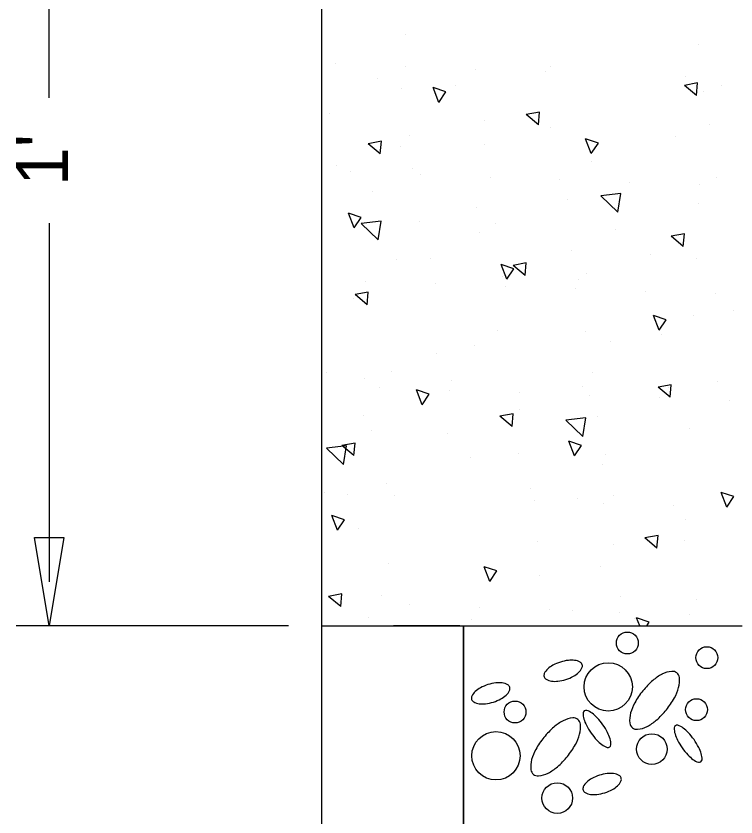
# Model space of a CAD drawing. Extents: x 0 to 8.5, y 0 to 11.
# Drawn here: x 4.506 to 5.34, y 7.415 to 8.342 of the extents above; entities that cross this region are included whole.
import ezdxf

# ---------------------------------------------------------------- set-up
doc = ezdxf.new("R2010")
doc.units = 0
for name, color, linetype in [('Default', 7, 'Continuous'), ('DTL-ASPHALT', 7, 'Continuous'), ('DTL-CONCRETE', 7, 'Continuous'), ('DTL-GRAVEL', 7, 'Continuous'), ('DTL-TEXT', 7, 'Continuous')]:
    doc.layers.add(name, color=color, linetype=linetype)

# ---------------------------------------------------------------- blocks, each defined once
blk = doc.blocks.new('POINT_DISPLAY')
at = {"layer": 'Default'}
blk.add_line((0, 0), (0, 0), dxfattribs=at)

msp = doc.modelspace()

# ---------------------------------------------------------------- linework, layer by layer
at = {"layer": 'DTL-ASPHALT'}
msp.add_lwpolyline([(5.02444, 7.05788), (4.86007, 7.05788), (4.86007, 7.63621), (5.02444, 7.63621)], close=True, dxfattribs=at)
at = {"layer": 'DTL-CONCRETE'}
for p, q in [((4.86007, 7.05788), (4.86007, 8.71374)), ((4.95736, 8.32082), (4.95736, 8.32082)), ((5.29682, 8.3088), (5.29682, 8.3088)), ((4.8758, 8.28674), (4.8758, 8.28674)), ((4.95686, 8.28378), (4.95686, 8.28378)), ((5.03792, 8.28082), (5.03792, 8.28082)), ((5.1249, 8.28374), (5.1249, 8.28374)), ((5.11899, 8.27786), (5.11899, 8.27786)), ((5.28111, 8.27193), (5.28111, 8.27193)), ((4.92465, 8.26947), (4.92465, 8.26947)), ((5.0154, 8.2623), (5.0154, 8.2623)), ((5.29557, 8.26477), (5.28031, 8.26196)), ((5.2943, 8.25022), (5.28031, 8.26196)), ((5.2943, 8.25022), (5.29557, 8.26477)), ((5.32376, 8.26158), (5.32376, 8.26158)), ((4.95307, 8.25807), (4.95307, 8.25807)), ((5.00401, 8.25435), (4.98929, 8.25929)), ((4.99584, 8.24223), (4.98929, 8.25928)), ((4.99584, 8.24223), (5.00401, 8.25435)), ((5.30213, 8.25515), (5.30213, 8.25515)), ((4.86916, 8.2299), (4.86916, 8.2299)), ((5.11241, 8.23099), (5.09714, 8.22817)), ((5.11113, 8.21643), (5.09714, 8.22817)), ((5.11113, 8.21643), (5.1124, 8.23099)), ((5.04843, 8.22103), (5.04843, 8.22103)), ((5.30896, 8.21658), (5.30896, 8.21658)), ((5.125, 8.21329), (5.125, 8.21329)), ((4.92924, 8.1972), (4.91398, 8.19438)), ((4.92796, 8.18264), (4.92924, 8.1972)), ((4.96193, 8.20395), (4.96193, 8.20395)), ((5.18059, 8.1951), (5.16587, 8.20004)), ((5.17242, 8.18298), (5.16587, 8.20003)), ((5.27029, 8.20324), (5.27029, 8.20324)), ((4.92796, 8.18264), (4.91397, 8.19438)), ((4.95187, 8.19083), (4.95187, 8.19083)), ((5.04911, 8.19401), (5.04911, 8.19401)), ((5.17242, 8.18298), (5.18059, 8.1951)), ((4.87719, 8.16894), (4.87719, 8.16894)), ((5.17286, 8.17361), (5.17286, 8.17361)), ((4.89294, 8.16171), (4.89294, 8.16171)), ((4.96521, 8.16584), (4.96521, 8.16584)), ((4.97401, 8.15875), (4.97401, 8.15875)), ((5.05507, 8.15579), (5.05507, 8.15579)), ((5.13613, 8.15283), (5.13613, 8.15283)), ((5.31699, 8.15562), (5.31699, 8.15562)), ((5.2172, 8.14987), (5.2172, 8.14987)), ((5.29826, 8.14691), (5.29826, 8.14691)), ((4.91916, 8.13948), (4.91916, 8.13948)), ((5.20646, 8.1369), (5.18333, 8.13421)), ((5.2031, 8.11524), (5.18333, 8.13421)), ((5.2031, 8.11524), (5.20646, 8.1369)), ((5.14515, 8.12995), (5.14515, 8.12995)), ((5.29664, 8.12516), (5.29664, 8.12516)), ((4.8978, 8.09688), (4.89125, 8.11393)), ((4.90597, 8.109), (4.89125, 8.11393)), ((5.03978, 8.12029), (5.03978, 8.12029)), ((4.8978, 8.09688), (4.90597, 8.10899)), ((4.92895, 8.10461), (4.90582, 8.10192)), ((4.92559, 8.08296), (4.92894, 8.10461)), ((4.97323, 8.10488), (4.97323, 8.10488)), ((4.92559, 8.08296), (4.90582, 8.10192)), ((5.06125, 8.10178), (5.06125, 8.10178)), ((5.20008, 8.09496), (5.20008, 8.09496)), ((5.04294, 8.09104), (5.04294, 8.09104)), ((5.28029, 8.09011), (5.26503, 8.0873)), ((5.27902, 8.07556), (5.26503, 8.0873)), ((5.27902, 8.07556), (5.28029, 8.09011)), ((5.14937, 8.07128), (5.14937, 8.07128)), ((4.94638, 8.06084), (4.94638, 8.06084)), ((4.98631, 8.06194), (4.98631, 8.06194)), ((5.24119, 8.06589), (5.24119, 8.06589)), ((5.29466, 8.06122), (5.29466, 8.06122)), ((5.07438, 8.03763), (5.06783, 8.05468)), ((5.08255, 8.04975), (5.06783, 8.05468)), ((5.07438, 8.03763), (5.08255, 8.04974)), ((5.09713, 8.05633), (5.08186, 8.05351)), ((5.09585, 8.04177), (5.08186, 8.05351)), ((5.09585, 8.04177), (5.09712, 8.05633)), ((5.06928, 8.04082), (5.06928, 8.04082)), ((5.16737, 8.04362), (5.16737, 8.04362)), ((4.9112, 8.03524), (4.9112, 8.03524)), ((4.99226, 8.03228), (4.99226, 8.03228)), ((5.15729, 8.03772), (5.15729, 8.03772)), ((4.91396, 8.02254), (4.8987, 8.01973)), ((4.91268, 8.00798), (4.91396, 8.02254)), ((5.07333, 8.02932), (5.07333, 8.02932)), ((5.15439, 8.02635), (5.15439, 8.02635)), ((5.23545, 8.02339), (5.23545, 8.02339)), ((5.31652, 8.02043), (5.31652, 8.02043)), ((4.89744, 8.01516), (4.89744, 8.01516)), ((4.91268, 8.00798), (4.89869, 8.01972)), ((4.91367, 8.00949), (4.91367, 8.00949)), ((5.33724, 8.00183), (5.33724, 8.00183)), ((5.25096, 7.97838), (5.24441, 7.99543)), ((5.25913, 7.9905), (5.24441, 7.99543)), ((5.29115, 7.99517), (5.29115, 7.99517)), ((5.25096, 7.97838), (5.25913, 7.99049)), ((5.06415, 7.97828), (5.06415, 7.97828)), ((5.16532, 7.97676), (5.16532, 7.97676)), ((5.19459, 7.96497), (5.19459, 7.96497)), ((5.25334, 7.97366), (5.25334, 7.97366)), ((5.03745, 7.96105), (5.03745, 7.96105)), ((4.99348, 7.9511), (4.99348, 7.9511)), ((4.86539, 7.92999), (4.86539, 7.92999)), ((4.94089, 7.93085), (4.94089, 7.93085)), ((5.17375, 7.92927), (5.17375, 7.92927)), ((4.90958, 7.92293), (4.90958, 7.92293)), ((5.01069, 7.91993), (5.01069, 7.91993)), ((5.31904, 7.91921), (5.31904, 7.91921)), ((4.92679, 7.91224), (4.92679, 7.91224)), ((4.97633, 7.89228), (4.96979, 7.90933)), ((4.98451, 7.90439), (4.96979, 7.90933)), ((5.00785, 7.90928), (5.00785, 7.90928)), ((5.16188, 7.91363), (5.16188, 7.91363)), ((5.26373, 7.9009), (5.24974, 7.91264)), ((5.26501, 7.91546), (5.24975, 7.91264)), ((5.26136, 7.9127), (5.26136, 7.9127)), ((5.26373, 7.9009), (5.26501, 7.91545)), ((4.97633, 7.89228), (4.9845, 7.90439)), ((5.08892, 7.90632), (5.08892, 7.90632)), ((5.16998, 7.90336), (5.16998, 7.90336)), ((5.25104, 7.9004), (5.25104, 7.9004)), ((5.33211, 7.89743), (5.33211, 7.89743)), ((5.08184, 7.88167), (5.06658, 7.87885)), ((5.08057, 7.86711), (5.08184, 7.88167)), ((5.08952, 7.88704), (5.08952, 7.88704)), ((4.90818, 7.8795), (4.90818, 7.8795)), ((5.08057, 7.86711), (5.06658, 7.87885)), ((5.16615, 7.87702), (5.14303, 7.87432)), ((5.16279, 7.85536), (5.14303, 7.87432)), ((5.16279, 7.85536), (5.16615, 7.87701)), ((5.28566, 7.86518), (5.28566, 7.86518)), ((4.9176, 7.86197), (4.9176, 7.86197)), ((5.00562, 7.85887), (5.00562, 7.85887)), ((4.88864, 7.84473), (4.86552, 7.84204)), ((4.89868, 7.84788), (4.88341, 7.84507)), ((4.8974, 7.83332), (4.88341, 7.84506)), ((4.88528, 7.82307), (4.88864, 7.84473)), ((4.8974, 7.83332), (4.89868, 7.84788)), ((5.15292, 7.83303), (5.14637, 7.85008)), ((5.16109, 7.84514), (5.14637, 7.85008)), ((5.15292, 7.83303), (5.16109, 7.84514)), ((4.88528, 7.82307), (4.86551, 7.84204)), ((5.08853, 7.83627), (5.08853, 7.83627)), ((5.1891, 7.83498), (5.1891, 7.83498)), ((5.03195, 7.83106), (5.03195, 7.83106)), ((5.18556, 7.82298), (5.18556, 7.82298)), ((4.93539, 7.80085), (4.93539, 7.80085)), ((4.86287, 7.79017), (4.86287, 7.79017)), ((5.10166, 7.79481), (5.10166, 7.79481)), ((5.3295, 7.77378), (5.32295, 7.79083)), ((5.33767, 7.78589), (5.32295, 7.79083)), ((4.88977, 7.78797), (4.88977, 7.78797)), ((4.94394, 7.78721), (4.94394, 7.78721)), ((5.10606, 7.78129), (5.10606, 7.78129)), ((5.15639, 7.78364), (5.15639, 7.78364)), ((5.19812, 7.78726), (5.19812, 7.78726)), ((5.3295, 7.77378), (5.33767, 7.78589)), ((5.18713, 7.77833), (5.18713, 7.77833)), ((5.26819, 7.77537), (5.26819, 7.77537)), ((4.87829, 7.74693), (4.87175, 7.76398)), ((4.88646, 7.75904), (4.87175, 7.76398)), ((4.87829, 7.74693), (4.88646, 7.75904)), ((5.28161, 7.75892), (5.28161, 7.75892)), ((4.90268, 7.74951), (4.90268, 7.74951)), ((5.10969, 7.73385), (5.10969, 7.73385)), ((5.24845, 7.72624), (5.23446, 7.73798)), ((5.24973, 7.7408), (5.23447, 7.73798)), ((5.24845, 7.72624), (5.24973, 7.74079)), ((5.28016, 7.73519), (5.28016, 7.73519)), ((5.19771, 7.73075), (5.19771, 7.73075)), ((4.93785, 7.70818), (4.93785, 7.70818)), ((5.1836, 7.70499), (5.1836, 7.70499)), ((5.05487, 7.68768), (5.04833, 7.70473)), ((5.06305, 7.69979), (5.04833, 7.70473)), ((5.05487, 7.68768), (5.06304, 7.69979)), ((5.11291, 7.69426), (5.11291, 7.69426)), ((4.8834, 7.67322), (4.86813, 7.67041)), ((4.88212, 7.65866), (4.86813, 7.6704)), ((4.88212, 7.65866), (4.8834, 7.67322)), ((4.9299, 7.67086), (4.9299, 7.67086)), ((5.20573, 7.66979), (5.20573, 7.66979)), ((4.88113, 7.6637), (4.88113, 7.6637)), ((4.96219, 7.66074), (4.96219, 7.66074)), ((5.29375, 7.66669), (5.29375, 7.66669)), ((5.04326, 7.65778), (5.04326, 7.65778)), ((5.12432, 7.65482), (5.12432, 7.65482)), ((5.15089, 7.65364), (5.15089, 7.65364)), ((5.20538, 7.65185), (5.20538, 7.65185)), ((4.91415, 7.64596), (4.91415, 7.64596)), ((5.03389, 7.64412), (5.03389, 7.64412)), ((5.2225, 7.64525), (5.2225, 7.64525)), ((5.22847, 7.63621), (5.22491, 7.64548)), ((5.23963, 7.64054), (5.22491, 7.64548)), ((5.23671, 7.63621), (5.23962, 7.64054)), ((5.28645, 7.64889), (5.28645, 7.64889)), ((4.86007, 7.63621), (5.34709, 7.63621)), ((5.02444, 7.05788), (5.02444, 7.63621))]:
    msp.add_line(p, q, dxfattribs=at)
at = {"layer": 'DTL-GRAVEL'}
for centre, radius in [((5.21418, 7.61639), 0.01265), ((5.30628, 7.59948), 0.01265), ((5.19203, 7.56567), 0.02797), ((5.08408, 7.5366), 0.01265), ((5.29431, 7.53927), 0.01265), ((5.06194, 7.48588), 0.02797), ((5.24258, 7.49361), 0.01775), ((5.13299, 7.43691), 0.01775)]:
    msp.add_circle(centre, radius, dxfattribs=at)
for centre, radius, start, end in [((5.1519, 7.54609), 0.05062, 107.58263, 118.27223), ((5.1519, 7.54609), 0.05062, 96.89302, 107.58263), ((5.14947, 7.56618), 0.03039, 83.08307, 96.89302), ((5.15112, 7.57979), 0.01667, 59.85119, 83.08307), ((5.15688, 7.58971), 0.0052, 17.58263, 59.85119), ((5.13312, 7.57409), 0.01667, 132.08218, 155.31406), ((5.14232, 7.56391), 0.03039, 118.27223, 132.08218), ((5.14646, 7.5945), 0.01667, 312.08218, 335.31406), ((5.15688, 7.58971), 0.0052, 335.31406, 17.58263), ((5.1227, 7.57888), 0.0052, 155.31406, 197.58263), ((5.1227, 7.57888), 0.0052, 197.58263, 239.85119), ((5.12769, 7.6225), 0.05062, 287.58263, 298.27223), ((5.13727, 7.60468), 0.03039, 298.27223, 312.08218), ((5.28043, 7.53078), 0.05598, 117.78613, 130.91747), ((5.26817, 7.55405), 0.02969, 95.0094, 117.78613), ((5.2663, 7.57541), 0.00824, 50.98289, 95.0094), ((5.2663, 7.57541), 0.00824, 6.95637, 50.98289), ((5.24501, 7.57282), 0.02969, 344.17965, 6.95637), ((5.06797, 7.51995), 0.05062, 107.58263, 118.27223), ((5.06797, 7.51995), 0.05062, 96.89302, 107.58263), ((5.06554, 7.54003), 0.03039, 83.08307, 96.89302), ((5.06719, 7.55365), 0.01667, 59.85119, 83.08307), ((5.07295, 7.56357), 0.0052, 17.58263, 59.85119), ((5.12846, 7.5888), 0.01667, 239.85119, 263.08307), ((5.13012, 7.60242), 0.03039, 263.08307, 276.89302), ((5.12769, 7.6225), 0.05062, 276.89302, 287.58263), ((5.30606, 7.50122), 0.09511, 130.91747, 140.98289), ((5.04919, 7.54795), 0.01667, 132.08218, 155.31406), ((5.05838, 7.53777), 0.03039, 118.27223, 132.08218), ((5.06253, 7.56836), 0.01667, 312.08218, 335.31406), ((5.07295, 7.56357), 0.0052, 335.31406, 17.58263), ((5.30606, 7.50122), 0.09511, 140.98289, 151.04831), ((5.21971, 7.57999), 0.05598, 331.04831, 344.17965), ((5.03877, 7.55274), 0.0052, 155.31406, 197.58263), ((5.03877, 7.55274), 0.0052, 197.58263, 239.85119), ((5.04453, 7.56266), 0.01667, 239.85119, 263.08307), ((5.04375, 7.59636), 0.05062, 276.89302, 287.58263), ((5.04375, 7.59636), 0.05062, 287.58263, 298.27223), ((5.05334, 7.57854), 0.03039, 298.27223, 312.08218), ((5.27182, 7.52016), 0.05598, 151.04831, 164.17965), ((5.18547, 7.59893), 0.09511, 320.98289, 331.04831), ((5.04618, 7.57627), 0.03039, 263.08307, 276.89302), ((5.16617, 7.53526), 0.00323, 73.22894, 125.09646), ((5.16125, 7.51894), 0.02028, 53.10914, 73.22894), ((5.18547, 7.59893), 0.09511, 310.91747, 320.98289), ((5.15352, 7.50009), 0.02969, 95.0094, 117.78613), ((5.15164, 7.52146), 0.00824, 50.98289, 95.0094), ((5.18319, 7.53436), 0.02028, 176.96398, 197.08379), ((5.16617, 7.53526), 0.00323, 125.09646, 176.96398), ((5.14747, 7.50058), 0.04324, 42.76732, 53.10914), ((5.12159, 7.47664), 0.0785, 35.09646, 42.76732), ((5.24652, 7.52733), 0.02969, 164.17965, 186.95637), ((5.16578, 7.47683), 0.05598, 117.78613, 130.91747), ((5.15164, 7.52146), 0.00824, 6.95637, 50.98289), ((5.13036, 7.51886), 0.02969, 344.17965, 6.95637), ((5.20514, 7.54111), 0.04324, 197.08379, 207.4256), ((5.23644, 7.55735), 0.0785, 207.4256, 215.09646), ((5.12159, 7.47664), 0.0785, 27.4256, 35.09646), ((5.22523, 7.52473), 0.00824, 186.95637, 230.98289), ((5.22336, 7.54609), 0.02969, 275.0094, 297.78613), ((5.2111, 7.56936), 0.05598, 297.78613, 310.91747), ((5.27177, 7.51807), 0.00323, 125.09646, 176.96398), ((5.27177, 7.51807), 0.00323, 73.22894, 125.09646), ((5.26685, 7.50176), 0.02028, 53.10914, 73.22894), ((5.1914, 7.44726), 0.09511, 130.91747, 140.98289), ((5.10505, 7.52603), 0.05598, 331.04831, 344.17965), ((5.23644, 7.55735), 0.0785, 215.09646, 222.76732), ((5.15288, 7.49288), 0.04324, 17.08379, 27.4256), ((5.22523, 7.52473), 0.00824, 230.98289, 275.0094), ((5.28879, 7.51717), 0.02028, 176.96398, 197.08379), ((5.31074, 7.52392), 0.04324, 197.08379, 207.4256), ((5.25307, 7.48339), 0.04324, 42.76732, 53.10914), ((5.22718, 7.45945), 0.0785, 35.09646, 42.76732), ((5.1914, 7.44726), 0.09511, 140.98289, 151.04831), ((5.21055, 7.5334), 0.04324, 222.76732, 233.10914), ((5.17483, 7.49962), 0.02028, 356.96398, 17.08379), ((5.34203, 7.54016), 0.0785, 207.4256, 215.09646), ((5.22718, 7.45945), 0.0785, 27.4256, 35.09646), ((5.15717, 7.4662), 0.05598, 151.04831, 164.17965), ((5.07082, 7.54497), 0.09511, 320.98289, 331.04831), ((5.19677, 7.51504), 0.02028, 233.10914, 253.22894), ((5.19185, 7.49872), 0.00323, 253.22894, 305.09646), ((5.19185, 7.49872), 0.00323, 305.09646, 356.96398), ((5.34203, 7.54016), 0.0785, 215.09646, 222.76732), ((5.25848, 7.47569), 0.04324, 17.08379, 27.4256), ((5.07082, 7.54497), 0.09511, 310.91747, 320.98289), ((5.31615, 7.51622), 0.04324, 222.76732, 233.10914), ((5.28043, 7.48244), 0.02028, 356.96398, 17.08379), ((5.13187, 7.47337), 0.02969, 164.17965, 186.95637), ((5.09644, 7.51541), 0.05598, 297.78613, 310.91747), ((5.30237, 7.49785), 0.02028, 233.10914, 253.22894), ((5.29745, 7.48153), 0.00323, 253.22894, 305.09646), ((5.29745, 7.48153), 0.00323, 305.09646, 356.96398), ((5.11058, 7.47078), 0.00824, 186.95637, 230.98289), ((5.11058, 7.47078), 0.00824, 230.98289, 275.0094), ((5.1087, 7.49214), 0.02969, 275.0094, 297.78613), ((5.19705, 7.41499), 0.05062, 96.89302, 107.58263), ((5.19462, 7.43508), 0.03039, 83.08307, 96.89302), ((5.19627, 7.4487), 0.01667, 59.85119, 83.08307), ((5.17827, 7.44299), 0.01667, 132.08218, 155.31406), ((5.18747, 7.43281), 0.03039, 118.27223, 132.08218), ((5.19705, 7.41499), 0.05062, 107.58263, 118.27223), ((5.19161, 7.46341), 0.01667, 312.08218, 335.31406), ((5.20203, 7.45862), 0.0052, 17.58263, 59.85119), ((5.20203, 7.45862), 0.0052, 335.31406, 17.58263), ((5.16785, 7.44778), 0.0052, 155.31406, 197.58263), ((5.16785, 7.44778), 0.0052, 197.58263, 239.85119), ((5.17284, 7.4914), 0.05062, 287.58263, 298.27223), ((5.18242, 7.47359), 0.03039, 298.27223, 312.08218), ((5.17361, 7.4577), 0.01667, 239.85119, 263.08307), ((5.17527, 7.47132), 0.03039, 263.08307, 276.89302), ((5.17284, 7.4914), 0.05062, 276.89302, 287.58263)]:
    msp.add_arc(centre, radius, start, end, dxfattribs=at)
at = {"layer": 'DTL-TEXT'}
for p, q in [((4.5443, 8.24751), (4.5443, 8.66254)), ((4.5443, 8.10244), (4.5443, 7.68741)), ((4.82167, 7.63621), (4.5059, 7.63621)), ((5.02019, 7.63621), (4.94334, 7.63621))]:
    msp.add_line(p, q, dxfattribs=at)
msp.add_lwpolyline([(4.56136, 7.73861), (4.5443, 7.63621), (4.52723, 7.73861)], close=True, dxfattribs=at)

# ---------------------------------------------------------------- block references
at = {"layer": 'DTL-CONCRETE', "xscale": 0.6400000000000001, "yscale": 0.6400000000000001, "rotation": 90}
for p in [(5.16265, 7.63668), (5.17972, 7.63668)]:
    msp.add_blockref('POINT_DISPLAY', p, dxfattribs=at)
at = {"layer": 'DTL-TEXT', "xscale": 0.6400000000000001, "yscale": 0.6400000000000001, "rotation": 90}
msp.add_blockref('POINT_DISPLAY', (5.17972, 7.87916), dxfattribs=at)

# ---------------------------------------------------------------- texts
at = {"layer": 'DTL-TEXT'}
msp.add_text("1'", height=0.06, rotation=90, dxfattribs=at).set_placement((4.56599, 8.14564))

doc.saveas('drawing.dxf')
